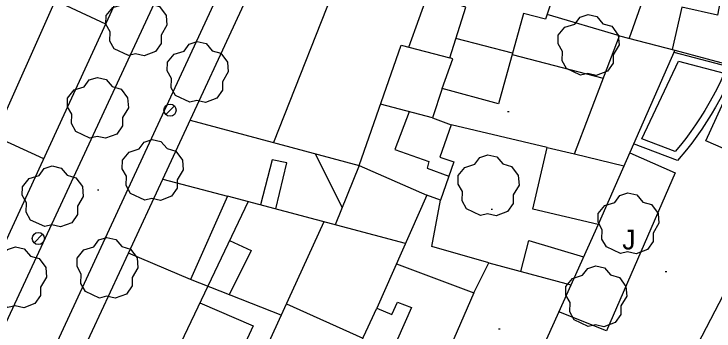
# Model space of a CAD drawing. Extents: x 431390 to 432653, y 4586754 to 4589600.
# Drawn here: x 432011.57 to 432057.54, y 4587690.53 to 4587711.36 of the extents above; entities that cross this region are included whole.
import ezdxf

# ---------------------------------------------------------------- set-up
doc = ezdxf.new("R2010")
doc.units = 0
for name, color, linetype in [('COM_17LS_LN', 7, 'Continuous'), ('CON_01_LN', 7, 'Continuous'), ('CON_01FI_LN', 7, 'Continuous'), ('CON_03_LN', 7, 'Continuous'), ('CON_04_LN', 7, 'Continuous'), ('CON_07_LN', 7, 'Continuous'), ('CON_15_LN', 7, 'Continuous'), ('CON_29_LN', 7, 'Continuous'), ('ENE_06_PT', 7, 'Continuous'), ('HID_11EX_LN', 7, 'Continuous'), ('HID_11IN_LN', 7, 'Continuous'), ('ORO_03_PT', 7, 'Continuous'), ('TOP_15JA_TX', 7, 'Continuous'), ('VEG_03_PT', 7, 'Continuous'), ('VEG_06_LN', 7, 'Continuous')]:
    doc.layers.add(name, color=color, linetype=linetype)

msp = doc.modelspace()

# ---------------------------------------------------------------- linework, layer by layer
at = {"layer": 'COM_17LS_LN'}
msp.add_lwpolyline([(432006.024, 4587680.292), (432041.411, 4587756.509), (432044.673, 4587755.098), (432041.441, 4587748.129), (432031.405, 4587726.494), (432019.334, 4587700.469), (432009.569, 4587679.418), (432092.063, 4587659.53)], dxfattribs=at)
at = {"layer": 'CON_01_LN'}
for points in [[(432021.338, 4587700.513), (432047.183, 4587756.23), (432074.462, 4587750.012), (432092.863, 4587741.826), (432089.971, 4587731.966), (432092.685, 4587729.526), (432096.818, 4587726.785), (432106.854, 4587721.265), (432088.661, 4587661.894), (432069.351, 4587666.555)], [(432028.804, 4587732.074), (432027.658, 4587732.613), (432004.401, 4587682.062), (431964.751, 4587691.684)], [(432054.971, 4587708.989), (432049.94, 4587697.527), (432045.645, 4587698.536), (432046.593, 4587702.58), (432048.373, 4587702.163), (432051.329, 4587709.927), (432054.971, 4587708.989)], [(432069.351, 4587666.555), (432012.008, 4587680.398), (432019.086, 4587695.657)]]:
    msp.add_lwpolyline(points, dxfattribs=at)
at = {"layer": 'CON_01FI_LN'}
for points in [[(432046.892, 4587724.422), (432044.444, 4587718.408), (432048.486, 4587717.066), (432046.486, 4587711.013), (432045.022, 4587711.398), (432043.392, 4587705.457), (432039.698, 4587706.471), (432039.061, 4587704.527), (432040.273, 4587704.088), (432039.533, 4587701.96), (432040.456, 4587701.644), (432039.581, 4587699.137), (432038.678, 4587699.459), (432035.4, 4587692.026), (432036.375, 4587691.621), (432036.759, 4587692.434), (432037.686, 4587692.072), (432036.767, 4587689.999)], [(432060.343, 4587701.59), (432057.017, 4587703.032), (432059.349, 4587708.158)], [(432055.373, 4587687.519), (432063.231, 4587702.643)], [(432021.338, 4587700.513), (432025.601, 4587699.397), (432023.153, 4587693.92), (432019.086, 4587695.657)]]:
    msp.add_lwpolyline(points, dxfattribs=at)
at = {"layer": 'CON_03_LN'}
for points in [[(432007.233, 4587715.55), (432017.579, 4587710.705)], [(432003.28, 4587706.545), (432013.51, 4587701.862)], [(432023.136, 4587704.389), (432034.242, 4587701.4), (432038.678, 4587699.459)], [(432037.277, 4587696.282), (432025.601, 4587699.397)], [(432026.951, 4587699.037), (432017.456, 4587679.083)], [(432031.928, 4587697.709), (432027.825, 4587688.744)], [(432028.171, 4587676.496), (432035.4, 4587692.026)]]:
    msp.add_lwpolyline(points, dxfattribs=at)
at = {"layer": 'CON_04_LN'}
for points in [[(432037.492, 4587709.174), (432038.853, 4587712.969)], [(432034.242, 4587701.4), (432036.989, 4587709.304), (432040.201, 4587708.477), (432041.241, 4587711.814), (432038.721, 4587712.601)], [(432044.303, 4587708.779), (432040.596, 4587709.745)], [(432039.698, 4587706.471), (432040.396, 4587708.418), (432040.201, 4587708.477)], [(432039.061, 4587704.527), (432035.643, 4587705.43)], [(432037.519, 4587704.934), (432036.592, 4587702.447), (432038.82, 4587701.662), (432038.702, 4587701.228), (432040.125, 4587700.697)], [(432033.133, 4587698.657), (432031.382, 4587702.17)], [(432048.373, 4587702.163), (432051.63, 4587701.377)], [(432028.775, 4587698.55), (432029.49, 4587701.571), (432028.52, 4587701.774), (432027.764, 4587698.82)], [(432034.242, 4587701.4), (432032.67, 4587697.511)], [(432025.733, 4587696.477), (432027.151, 4587695.818), (432025.701, 4587692.919)], [(432029.121, 4587691.575), (432023.153, 4587693.92)], [(432023.785, 4587692.384), (432027.29, 4587690.869), (432025.533, 4587687.079), (432026.794, 4587686.492)], [(432029.462, 4587692.321), (432034.488, 4587690.066)]]:
    msp.add_lwpolyline(points, dxfattribs=at)
at = {"layer": 'CON_07_LN'}
for points in [[(432059.589, 4587708.087), (432060.945, 4587713.924), (432058.362, 4587714.438), (432057.773, 4587711.281), (432055.427, 4587711.804), (432054.791, 4587709.035)], [(432054.971, 4587708.989), (432059.21, 4587707.853)], [(432036.685, 4587694.94), (432041.76, 4587693.043), (432042.749, 4587695.01), (432039.011, 4587696.09), (432039.581, 4587699.137)], [(432044.865, 4587694.443), (432045.389, 4587696.479), (432048.981, 4587695.404)]]:
    msp.add_lwpolyline(points, dxfattribs=at)
at = {"layer": 'CON_15_LN'}
for points in [[(432052.946, 4587712.565), (432051.966, 4587709.763)], [(432051.329, 4587709.927), (432046.586, 4587711.316)], [(432044.279, 4587708.691), (432050.271, 4587707.148)], [(432046.593, 4587702.58), (432040.273, 4587704.088)], [(432019.086, 4587695.657), (432021.338, 4587700.513)], [(432049.94, 4587697.527), (432045.332, 4587687.328)], [(432042.749, 4587695.01), (432048.149, 4587693.564)], [(432041.76, 4587693.043), (432040.023, 4587689.014)]]:
    msp.add_lwpolyline(points, dxfattribs=at)
at = {"layer": 'CON_29_LN'}
for points in [[(432033.156, 4587714.42), (432028.619, 4587702.913)], [(432014.269, 4587712.255), (432010.282, 4587703.34)]]:
    msp.add_lwpolyline(points, dxfattribs=at)
at = {"layer": 'ENE_06_PT'}
for p, q in [((432022.103, 4587705.329), (432021.537, 4587704.763)), ((432013.453, 4587696.896), (432012.887, 4587696.33))]:
    msp.add_line(p, q, dxfattribs=at)
for centre in [(432021.82, 4587705.046), (432013.17, 4587696.613)]:
    msp.add_circle(centre, 0.4, dxfattribs=at)
at = {"layer": 'HID_11EX_LN'}
msp.add_lwpolyline([(432054.913, 4587708.856), (432058.918, 4587707.794), (432058.436, 4587706.745), (432058.186, 4587706.236), (432057.923, 4587705.734), (432057.647, 4587705.241), (432057.359, 4587704.752), (432057.057, 4587704.273), (432056.744, 4587703.802), (432056.419, 4587703.338), (432056.081, 4587702.883), (432055.731, 4587702.438), (432055.147, 4587701.731), (432052.264, 4587702.822)], dxfattribs=at)
at = {"layer": 'HID_11IN_LN'}
msp.add_lwpolyline([(432052.797, 4587703.156), (432055.203, 4587708.262), (432058.216, 4587707.463), (432057.985, 4587706.96), (432057.741, 4587706.463), (432057.484, 4587705.973), (432057.214, 4587705.49), (432056.933, 4587705.013), (432056.638, 4587704.545), (432056.332, 4587704.084), (432056.014, 4587703.631), (432055.684, 4587703.187), (432055.342, 4587702.752), (432054.99, 4587702.326), (432052.797, 4587703.156)], dxfattribs=at)
at = {"layer": 'ORO_03_PT'}
for p, q in [((432043.99, 4587704.954), (432044.09, 4587704.954)), ((432017.051, 4587699.808), (432017.151, 4587699.808)), ((432042.906, 4587698.537), (432043.006, 4587698.537)), ((432054.343, 4587694.439), (432054.443, 4587694.439)), ((432043.399, 4587690.669), (432043.499, 4587690.669))]:
    msp.add_line(p, q, dxfattribs=at)
at = {"layer": 'VEG_03_PT'}
for points in [[(432019.086, 4587708.628), (432018.159, 4587709.063), (432017.871, 4587709.584), (432017.894, 4587710.198), (432017.612, 4587710.69), (432017.62, 4587711.253), (432018.061, 4587711.788), (432018.714, 4587711.992), (432019.049, 4587712.443), (432019.575, 4587712.613), (432020.155, 4587712.48), (432020.555, 4587712.014), (432021.129, 4587711.844), (432021.563, 4587711.261), (432021.612, 4587710.619), (432021.229, 4587709.972), (432021.229, 4587709.422), (432020.857, 4587708.888), (432020.118, 4587708.613), (432019.553, 4587708.741), (432019.086, 4587708.628)], [(432048.781, 4587707.335), (432047.854, 4587707.77), (432047.566, 4587708.291), (432047.589, 4587708.905), (432047.307, 4587709.397), (432047.315, 4587709.96), (432047.756, 4587710.495), (432048.409, 4587710.699), (432048.744, 4587711.15), (432049.27, 4587711.32), (432049.85, 4587711.187), (432050.25, 4587710.721), (432050.824, 4587710.551), (432051.258, 4587709.968), (432051.307, 4587709.326), (432050.924, 4587708.679), (432050.924, 4587708.129), (432050.552, 4587707.595), (432049.813, 4587707.32), (432049.248, 4587707.448), (432048.781, 4587707.335)], [(432023.116, 4587705.56), (432022.189, 4587705.995), (432021.901, 4587706.516), (432021.924, 4587707.13), (432021.642, 4587707.622), (432021.65, 4587708.185), (432022.091, 4587708.72), (432022.744, 4587708.924), (432023.079, 4587709.375), (432023.605, 4587709.545), (432024.185, 4587709.412), (432024.585, 4587708.946), (432025.159, 4587708.776), (432025.593, 4587708.193), (432025.642, 4587707.551), (432025.259, 4587706.904), (432025.259, 4587706.354), (432024.887, 4587705.82), (432024.148, 4587705.545), (432023.583, 4587705.673), (432023.116, 4587705.56)], [(432016.557, 4587703.208), (432015.63, 4587703.643), (432015.342, 4587704.164), (432015.365, 4587704.778), (432015.083, 4587705.27), (432015.091, 4587705.833), (432015.532, 4587706.368), (432016.185, 4587706.572), (432016.52, 4587707.023), (432017.046, 4587707.193), (432017.626, 4587707.06), (432018.026, 4587706.594), (432018.6, 4587706.424), (432019.034, 4587705.841), (432019.083, 4587705.199), (432018.7, 4587704.552), (432018.7, 4587704.002), (432018.328, 4587703.468), (432017.589, 4587703.193), (432017.024, 4587703.321), (432016.557, 4587703.208)], [(432020.156, 4587699.13), (432019.229, 4587699.565), (432018.941, 4587700.086), (432018.964, 4587700.7), (432018.682, 4587701.192), (432018.69, 4587701.755), (432019.131, 4587702.29), (432019.784, 4587702.494), (432020.119, 4587702.945), (432020.645, 4587703.115), (432021.225, 4587702.982), (432021.625, 4587702.516), (432022.199, 4587702.346), (432022.633, 4587701.763), (432022.682, 4587701.121), (432022.299, 4587700.474), (432022.299, 4587699.924), (432021.927, 4587699.39), (432021.188, 4587699.115), (432020.623, 4587699.243), (432020.156, 4587699.13)], [(432042.211, 4587698.125), (432041.284, 4587698.56), (432040.996, 4587699.081), (432041.019, 4587699.695), (432040.737, 4587700.187), (432040.745, 4587700.75), (432041.186, 4587701.285), (432041.839, 4587701.489), (432042.174, 4587701.94), (432042.7, 4587702.11), (432043.28, 4587701.977), (432043.68, 4587701.511), (432044.254, 4587701.341), (432044.688, 4587700.758), (432044.737, 4587700.116), (432044.354, 4587699.469), (432044.354, 4587698.919), (432043.982, 4587698.385), (432043.243, 4587698.11), (432042.678, 4587698.238), (432042.211, 4587698.125)], [(432013.593, 4587697.389), (432012.666, 4587697.824), (432012.378, 4587698.345), (432012.401, 4587698.959), (432012.119, 4587699.451), (432012.127, 4587700.014), (432012.568, 4587700.549), (432013.221, 4587700.753), (432013.556, 4587701.204), (432014.082, 4587701.374), (432014.662, 4587701.241), (432015.062, 4587700.775), (432015.636, 4587700.605), (432016.07, 4587700.022), (432016.119, 4587699.38), (432015.736, 4587698.733), (432015.736, 4587698.183), (432015.364, 4587697.649), (432014.625, 4587697.374), (432014.06, 4587697.502), (432013.593, 4587697.389)], [(432051.401, 4587695.619), (432050.474, 4587696.054), (432050.186, 4587696.575), (432050.209, 4587697.189), (432049.927, 4587697.681), (432049.935, 4587698.244), (432050.376, 4587698.779), (432051.029, 4587698.983), (432051.364, 4587699.434), (432051.89, 4587699.604), (432052.47, 4587699.471), (432052.87, 4587699.005), (432053.444, 4587698.835), (432053.878, 4587698.252), (432053.927, 4587697.61), (432053.544, 4587696.963), (432053.544, 4587696.413), (432053.172, 4587695.879), (432052.433, 4587695.604), (432051.868, 4587695.732), (432051.401, 4587695.619)], [(432017.186, 4587692.7), (432016.259, 4587693.135), (432015.971, 4587693.656), (432015.994, 4587694.27), (432015.712, 4587694.762), (432015.72, 4587695.325), (432016.161, 4587695.86), (432016.814, 4587696.064), (432017.149, 4587696.515), (432017.675, 4587696.685), (432018.255, 4587696.552), (432018.655, 4587696.086), (432019.229, 4587695.916), (432019.663, 4587695.333), (432019.712, 4587694.691), (432019.329, 4587694.044), (432019.329, 4587693.494), (432018.957, 4587692.96), (432018.218, 4587692.685), (432017.653, 4587692.813), (432017.186, 4587692.7)], [(432011.179, 4587692.072), (432010.252, 4587692.507), (432009.964, 4587693.028), (432009.987, 4587693.642), (432009.705, 4587694.134), (432009.713, 4587694.697), (432010.154, 4587695.232), (432010.807, 4587695.436), (432011.142, 4587695.887), (432011.668, 4587696.057), (432012.248, 4587695.924), (432012.648, 4587695.458), (432013.222, 4587695.288), (432013.656, 4587694.705), (432013.705, 4587694.063), (432013.322, 4587693.416), (432013.322, 4587692.866), (432012.95, 4587692.332), (432012.211, 4587692.057), (432011.646, 4587692.185), (432011.179, 4587692.072)], [(432049.284, 4587690.833), (432048.357, 4587691.268), (432048.069, 4587691.789), (432048.092, 4587692.403), (432047.81, 4587692.895), (432047.818, 4587693.458), (432048.259, 4587693.993), (432048.912, 4587694.197), (432049.247, 4587694.648), (432049.773, 4587694.818), (432050.353, 4587694.685), (432050.753, 4587694.219), (432051.327, 4587694.049), (432051.761, 4587693.466), (432051.81, 4587692.824), (432051.427, 4587692.177), (432051.427, 4587691.627), (432051.055, 4587691.093), (432050.316, 4587690.818), (432049.751, 4587690.946), (432049.284, 4587690.833)]]:
    msp.add_lwpolyline(points, dxfattribs=at)
at = {"layer": 'VEG_06_LN'}
msp.add_lwpolyline([(432052.01, 4587702.243), (432054.993, 4587700.923), (432050.484, 4587690.546), (432047.347, 4587691.789)], dxfattribs=at)

# ---------------------------------------------------------------- texts
at = {"layer": 'TOP_15JA_TX'}
msp.add_text('J', height=1.3, dxfattribs=at).set_placement((432051.519, 4587695.887))

doc.saveas('drawing.dxf')
